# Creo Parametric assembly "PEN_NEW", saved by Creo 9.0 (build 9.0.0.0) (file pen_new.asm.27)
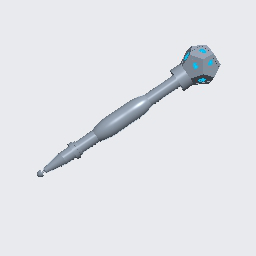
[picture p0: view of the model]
Units: millimeter Newton Second (mmNs); MM, TONNE, SECS

Created from: PEN.ASM

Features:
  1. component "01_STYLUS_HALF", "STYLUS_BOTTOM_V2.PRT"
  2. component "02_NIB_HOLDER", "NIB_HOLDER.PRT"
  3. component "03_NIB_BASE", "NIB_BASE.PRT"
  4. component "04_METAL_ROD", "METAL_ROD.PRT"
  5. component "01_STYLUS_HALF", "STYLUS_BOTTOM_V2.PRT"
  6. component "05_RING", "RING.PRT"
  7. component "06_DODECA_STYLUS_HALF", "DODECA_STYLUS_HALF.PRT"
  8. component "07_D_RING", "D_RING.PRT"
  9. component "08_DODECA_LID", "DODECA_LID.PRT"
  10. component "09_TIP", "TIP.PRT"

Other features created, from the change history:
  component "DODECA_V3.PRT"
  component "XIAO-NRF52840_V15.ASM"
  component "STYLUS-TOP.PRT"
  component "DODECA_V3_BOTTOM.PRT"
  component "DODECA.ASM"
  component "NIB_BASE.PRT"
